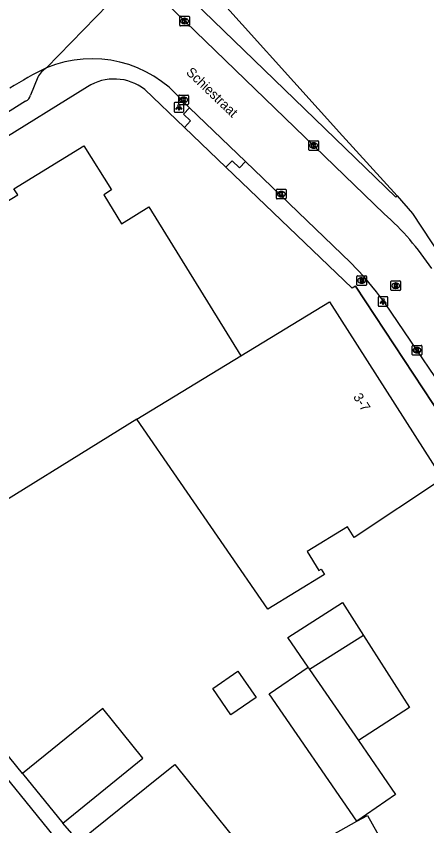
# Model space of a CAD drawing. Extents: x 157321 to 158827, y 386650 to 388532.
# Drawn here: x 157396.2 to 157438.5, y 387596.5 to 387680.1 of the extents above; entities that cross this region are included whole.
import ezdxf

# ---------------------------------------------------------------- set-up
doc = ezdxf.new("R2010")
doc.units = 0
for name, color, linetype in [('IMGEO_Brandkraan', 7, 'Continuous'), ('IMGEO_Erf', 7, 'Continuous'), ('IMGEO_Greppel_droge_sloot', 7, 'Continuous'), ('IMGEO_Groenvoorziening', 7, 'Continuous'), ('IMGEO_Kolk', 7, 'Continuous'), ('IMGEO_Lichtpunt', 7, 'Continuous'), ('IMGEO_Muur', 7, 'Continuous'), ('IMGEO_Openbare_ruimte_label', 7, 'Continuous'), ('IMGEO_Pand', 7, 'Continuous'), ('IMGEO_Pand_nummerreeks', 7, 'Continuous'), ('IMGEO_Rijbaan_lokaal_open', 7, 'Continuous'), ('IMGEO_Rioolput', 7, 'Continuous'), ('IMGEO_Voetpad_open', 7, 'Continuous')]:
    doc.layers.add(name, color=color, linetype=linetype)

msp = doc.modelspace()

# ---------------------------------------------------------------- linework, layer by layer
at = {"layer": 'IMGEO_Brandkraan'}
for p, q in [((157431.307, 387652.411), (157431.307, 387653.263)), ((157431.382, 387653.337), (157432.234, 387653.337)), ((157431.795, 387653.117), (157431.82, 387653.117)), ((157432.308, 387653.263), (157432.308, 387652.411)), ((157432.234, 387652.337), (157431.382, 387652.337)), ((157431.818, 387652.557), (157431.793, 387652.557))]:
    msp.add_line(p, q, dxfattribs=at)
for points in [[(157431.307, 387652.411), (157431.307, 387653.263)], [(157431.382, 387653.337), (157432.234, 387653.337)], [(157431.655, 387653.037), (157431.655, 387652.637), (157431.868, 387652.637)], [(157431.886, 387653.037), (157431.655, 387653.037)], [(157432.308, 387653.263), (157432.308, 387652.411)], [(157432.234, 387652.337), (157431.382, 387652.337)], [(157431.834, 387652.956), (157431.78, 387652.956), (157431.78, 387652.88)], [(157431.78, 387652.88), (157431.833, 387652.88)], [(157431.842, 387652.804), (157431.78, 387652.804), (157431.78, 387652.723)], [(157431.78, 387652.723), (157431.842, 387652.723)]]:
    msp.add_lwpolyline(points, dxfattribs=at)
for centre, radius, start, end in [((157431.384, 387653.261), 0.0765, 91.55205, 178.44795), ((157431.384, 387653.261), 0.0765, 91.55205, 178.44795), ((157431.89, 387652.892), 0.145, 59.4692, 91.53667), ((157431.915, 387652.939), 0.0922, 285.51372, 58.15012), ((157432.232, 387653.261), 0.0765, 1.55205, 88.44795), ((157432.232, 387653.261), 0.0765, 1.55205, 88.44795), ((157431.384, 387652.413), 0.0765, 181.55205, 268.44795), ((157431.384, 387652.413), 0.0765, 181.55205, 268.44795), ((157431.835, 387652.918), 0.0379, 267.82845, 90.93552), ((157431.843, 387652.763), 0.0404, 269.87594, 90.50774), ((157431.874, 387652.888), 0.251, 268.66757, 293.53466), ((157431.92, 387652.747), 0.105, 301.31148, 78.98903), ((157432.232, 387652.413), 0.0765, 271.55205, 358.44795), ((157432.232, 387652.413), 0.0765, 271.55205, 358.44795)]:
    msp.add_arc(centre, radius, start, end, dxfattribs=at)
for centre, major_axis, ratio, start_param, end_param in [((157431.794, 387652.837), (-0.387, 0.002), 0.722429, 4.712389, 7.853982), ((157431.819, 387652.837), (-0.39, 0.002), 0.717154, 1.570796, 4.712389)]:
    msp.add_ellipse(centre, major_axis=major_axis, ratio=ratio, start_param=start_param, end_param=end_param, dxfattribs=at)
at = {"layer": 'IMGEO_Erf'}
for points in [[(157396.827, 387601.943), (157374.839, 387629.111), (157367.841, 387637.744)], [(157402.618, 387594.917), (157400.97, 387596.826)]]:
    msp.add_lwpolyline(points, dxfattribs=at)
at = {"layer": 'IMGEO_Greppel_droge_sloot'}
msp.add_lwpolyline([(157364.956, 387637.663), (157366.252, 387637.187), (157406.382, 387587.613), (157407.121, 387586.787), (157407.417, 387584.957), (157406.631, 387583.97), (157405.344, 387583.565), (157404.654, 387583.712), (157404.061, 387584.031), (157403.357, 387584.76), (157364.055, 387633.408), (157363.304, 387634.511), (157362.971, 387635.617), (157363.13, 387636.647), (157363.942, 387637.488), (157364.956, 387637.663)], dxfattribs=at)
at = {"layer": 'IMGEO_Groenvoorziening'}
msp.add_lwpolyline([(157425.585, 387732.533), (157423.705, 387722.067), (157425.177, 387721.431), (157414.446, 387684.901), (157429.844, 387667.778), (157435.461, 387661.595)], dxfattribs=at)
at = {"layer": 'IMGEO_Kolk'}
for p, q in [((157413.036, 387679.217), (157413.036, 387680.069)), ((157413.111, 387680.143), (157413.963, 387680.143)), ((157413.524, 387679.923), (157413.549, 387679.923)), ((157414.037, 387680.069), (157414.037, 387679.217)), ((157413.963, 387679.143), (157413.111, 387679.143)), ((157413.547, 387679.363), (157413.522, 387679.363)), ((157412.936, 387671.077), (157412.936, 387671.929)), ((157413.011, 387672.003), (157413.863, 387672.003)), ((157413.424, 387671.783), (157413.449, 387671.783)), ((157413.937, 387671.929), (157413.937, 387671.077)), ((157413.863, 387671.003), (157413.011, 387671.003)), ((157413.447, 387671.223), (157413.422, 387671.223)), ((157426.355, 387666.354), (157426.355, 387667.206)), ((157426.43, 387667.28), (157427.282, 387667.28)), ((157427.356, 387667.206), (157427.356, 387666.354)), ((157426.866, 387666.5), (157426.841, 387666.5)), ((157426.843, 387667.06), (157426.868, 387667.06)), ((157427.282, 387666.28), (157426.43, 387666.28)), ((157423.011, 387661.349), (157423.011, 387662.201)), ((157423.086, 387662.275), (157423.938, 387662.275)), ((157424.012, 387662.201), (157424.012, 387661.349)), ((157423.522, 387661.495), (157423.497, 387661.495)), ((157423.499, 387662.055), (157423.524, 387662.055)), ((157423.938, 387661.275), (157423.086, 387661.275)), ((157437.019, 387645.218), (157437.019, 387646.07)), ((157437.094, 387646.144), (157437.946, 387646.144)), ((157437.507, 387645.924), (157437.532, 387645.924)), ((157438.02, 387646.07), (157438.02, 387645.218)), ((157437.946, 387645.144), (157437.094, 387645.144)), ((157437.53, 387645.364), (157437.505, 387645.364))]:
    msp.add_line(p, q, dxfattribs=at)
for points in [[(157413.036, 387679.217), (157413.036, 387680.069)], [(157413.111, 387680.143), (157413.963, 387680.143)], [(157413.357, 387679.843), (157413.48, 387679.843), (157413.48, 387679.692), (157413.61, 387679.843), (157413.774, 387679.843), (157413.628, 387679.692), (157413.781, 387679.443), (157413.629, 387679.443), (157413.544, 387679.607), (157413.48, 387679.54), (157413.48, 387679.443), (157413.357, 387679.443), (157413.357, 387679.843)], [(157414.037, 387680.069), (157414.037, 387679.217)], [(157413.963, 387679.143), (157413.111, 387679.143)], [(157412.936, 387671.077), (157412.936, 387671.929)], [(157413.011, 387672.003), (157413.863, 387672.003)], [(157413.257, 387671.703), (157413.38, 387671.703), (157413.38, 387671.552), (157413.51, 387671.703), (157413.674, 387671.703), (157413.528, 387671.552), (157413.681, 387671.303), (157413.529, 387671.303), (157413.444, 387671.467), (157413.38, 387671.4), (157413.38, 387671.303), (157413.257, 387671.303), (157413.257, 387671.703)], [(157413.937, 387671.929), (157413.937, 387671.077)], [(157413.863, 387671.003), (157413.011, 387671.003)], [(157426.355, 387666.354), (157426.355, 387667.206)], [(157426.43, 387667.28), (157427.282, 387667.28)], [(157427.356, 387667.206), (157427.356, 387666.354)], [(157426.676, 387666.98), (157426.799, 387666.98), (157426.799, 387666.829), (157426.929, 387666.98), (157427.093, 387666.98), (157426.947, 387666.829), (157427.1, 387666.58), (157426.948, 387666.58), (157426.863, 387666.744), (157426.799, 387666.677), (157426.799, 387666.58), (157426.676, 387666.58), (157426.676, 387666.98)], [(157427.282, 387666.28), (157426.43, 387666.28)], [(157423.011, 387661.349), (157423.011, 387662.201)], [(157423.086, 387662.275), (157423.938, 387662.275)], [(157424.012, 387662.201), (157424.012, 387661.349)], [(157423.332, 387661.975), (157423.455, 387661.975), (157423.455, 387661.824), (157423.585, 387661.975), (157423.749, 387661.975), (157423.603, 387661.824), (157423.756, 387661.575), (157423.604, 387661.575), (157423.519, 387661.739), (157423.455, 387661.672), (157423.455, 387661.575), (157423.332, 387661.575), (157423.332, 387661.975)], [(157423.938, 387661.275), (157423.086, 387661.275)], [(157437.019, 387645.218), (157437.019, 387646.07)], [(157437.094, 387646.144), (157437.946, 387646.144)], [(157437.34, 387645.844), (157437.463, 387645.844), (157437.463, 387645.693), (157437.593, 387645.844), (157437.757, 387645.844), (157437.611, 387645.693), (157437.764, 387645.444), (157437.612, 387645.444), (157437.527, 387645.608), (157437.463, 387645.541), (157437.463, 387645.444), (157437.34, 387645.444), (157437.34, 387645.844)], [(157438.02, 387646.07), (157438.02, 387645.218)], [(157437.946, 387645.144), (157437.094, 387645.144)]]:
    msp.add_lwpolyline(points, dxfattribs=at)
for centre, start, end in [((157413.113, 387680.067), 91.55205, 178.44795), ((157413.113, 387680.067), 91.55205, 178.44795), ((157413.961, 387680.067), 1.55205, 88.44795), ((157413.961, 387680.067), 1.55205, 88.44795), ((157413.113, 387679.219), 181.55205, 268.44795), ((157413.113, 387679.219), 181.55205, 268.44795), ((157413.961, 387679.219), 271.55205, 358.44795), ((157413.961, 387679.219), 271.55205, 358.44795), ((157413.013, 387671.927), 91.55205, 178.44795), ((157413.013, 387671.927), 91.55205, 178.44795), ((157413.861, 387671.927), 1.55205, 88.44795), ((157413.861, 387671.927), 1.55205, 88.44795), ((157413.013, 387671.079), 181.55205, 268.44795), ((157413.013, 387671.079), 181.55205, 268.44795), ((157413.861, 387671.079), 271.55205, 358.44795), ((157413.861, 387671.079), 271.55205, 358.44795), ((157426.432, 387667.204), 91.55205, 178.44795), ((157426.432, 387667.204), 91.55205, 178.44795), ((157427.28, 387667.204), 1.55205, 88.44795), ((157427.28, 387667.204), 1.55205, 88.44795), ((157426.432, 387666.356), 181.55205, 268.44795), ((157426.432, 387666.356), 181.55205, 268.44795), ((157427.28, 387666.356), 271.55205, 358.44795), ((157427.28, 387666.356), 271.55205, 358.44795), ((157423.088, 387662.199), 91.55205, 178.44795), ((157423.088, 387662.199), 91.55205, 178.44795), ((157423.936, 387662.199), 1.55205, 88.44795), ((157423.936, 387662.199), 1.55205, 88.44795), ((157423.088, 387661.351), 181.55205, 268.44795), ((157423.088, 387661.351), 181.55205, 268.44795), ((157423.936, 387661.351), 271.55205, 358.44795), ((157423.936, 387661.351), 271.55205, 358.44795), ((157437.096, 387646.068), 91.55205, 178.44795), ((157437.096, 387646.068), 91.55205, 178.44795), ((157437.944, 387646.068), 1.55205, 88.44795), ((157437.944, 387646.068), 1.55205, 88.44795), ((157437.096, 387645.22), 181.55205, 268.44795), ((157437.096, 387645.22), 181.55205, 268.44795), ((157437.944, 387645.22), 271.55205, 358.44795), ((157437.944, 387645.22), 271.55205, 358.44795)]:
    msp.add_arc(centre, 0.0765, start, end, dxfattribs=at)
for centre, major_axis, ratio, start_param, end_param in [((157413.523, 387679.643), (-0.387, 0.002), 0.722429, 4.712389, 7.853982), ((157413.548, 387679.643), (-0.39, 0.002), 0.717154, 1.570796, 4.712389), ((157413.423, 387671.503), (-0.387, 0.002), 0.722429, 4.712389, 7.853982), ((157413.448, 387671.503), (-0.39, 0.002), 0.717154, 1.570796, 4.712389), ((157426.842, 387666.78), (-0.387, 0.002), 0.722429, 4.712389, 7.853982), ((157426.867, 387666.78), (-0.39, 0.002), 0.717154, 1.570796, 4.712389), ((157423.498, 387661.775), (-0.387, 0.002), 0.722429, 4.712389, 7.853982), ((157423.523, 387661.775), (-0.39, 0.002), 0.717154, 1.570796, 4.712389), ((157437.506, 387645.644), (-0.387, 0.002), 0.722429, 4.712389, 7.853982), ((157437.531, 387645.644), (-0.39, 0.002), 0.717154, 1.570796, 4.712389)]:
    msp.add_ellipse(centre, major_axis=major_axis, ratio=ratio, start_param=start_param, end_param=end_param, dxfattribs=at)
at = {"layer": 'IMGEO_Lichtpunt'}
for p, q in [((157412.45, 387671.134), (157412.45, 387670.327)), ((157412.45, 387671.134), (157412.45, 387670.327)), ((157413.352, 387671.229), (157412.544, 387671.229)), ((157413.352, 387671.229), (157412.544, 387671.229)), ((157413.446, 387670.327), (157413.446, 387671.134)), ((157413.446, 387670.327), (157413.446, 387671.134)), ((157412.544, 387670.233), (157413.352, 387670.233)), ((157412.544, 387670.233), (157413.352, 387670.233)), ((157433.516, 387651.084), (157433.516, 387650.277)), ((157433.516, 387651.084), (157433.516, 387650.277)), ((157434.418, 387651.179), (157433.61, 387651.179)), ((157434.418, 387651.179), (157433.61, 387651.179)), ((157434.512, 387650.277), (157434.512, 387651.084)), ((157434.512, 387650.277), (157434.512, 387651.084)), ((157433.61, 387650.183), (157434.418, 387650.183)), ((157433.61, 387650.183), (157434.418, 387650.183))]:
    msp.add_line(p, q, dxfattribs=at)
for points in [[(157412.824, 387670.798), (157412.863, 387670.77), (157412.675, 387670.508), (157412.637, 387670.535), (157412.824, 387670.798)], [(157412.926, 387670.75), (157412.973, 387670.75), (157412.973, 387670.428), (157412.926, 387670.428), (157412.926, 387670.75)], [(157413.036, 387670.77), (157413.074, 387670.797), (157413.261, 387670.535), (157413.222, 387670.507), (157413.036, 387670.77)], [(157433.89, 387650.748), (157433.929, 387650.72), (157433.741, 387650.458), (157433.703, 387650.485), (157433.89, 387650.748)], [(157433.992, 387650.7), (157434.039, 387650.7), (157434.039, 387650.378), (157433.992, 387650.378), (157433.992, 387650.7)], [(157434.102, 387650.72), (157434.14, 387650.747), (157434.327, 387650.485), (157434.288, 387650.457), (157434.102, 387650.72)]]:
    msp.add_lwpolyline(points, dxfattribs=at)
for centre in [(157412.949, 387670.932), (157434.015, 387650.882)]:
    msp.add_circle(centre, 0.0994, dxfattribs=at)
for centre, start, end in [((157412.544, 387671.134), 90, 180), ((157412.544, 387671.134), 90, 180), ((157413.352, 387671.134), 0, 90), ((157413.352, 387671.134), 0, 90), ((157412.544, 387670.327), 180, 270), ((157412.544, 387670.327), 180, 270), ((157413.352, 387670.327), 270, 0), ((157413.352, 387670.327), 270, 360), ((157433.61, 387651.084), 90, 180), ((157433.61, 387651.084), 90, 180), ((157434.418, 387651.084), 0, 90), ((157434.418, 387651.084), 0, 90), ((157433.61, 387650.277), 180, 270), ((157433.61, 387650.277), 180, 270), ((157434.418, 387650.277), 270, 0), ((157434.418, 387650.277), 270, 360)]:
    msp.add_arc(centre, 0.0946, start, end, dxfattribs=at)
at = {"layer": 'IMGEO_Muur'}
msp.add_lwpolyline([(157431.16, 387652.274), (157441.141, 387637.118)], dxfattribs=at)
at = {"layer": 'IMGEO_Pand'}
for points in [[(157408.617, 387638.531), (157390.176, 387627.112), (157378.757, 387641.186), (157381.806, 387643.081), (157377.054, 387650.725), (157383.572, 387654.776), (157384.062, 387653.961), (157385.72, 387654.996), (157385.229, 387655.786), (157387.738, 387657.347), (157388.139, 387656.695), (157396.315, 387661.696), (157395.933, 387662.318), (157403.154, 387666.754), (157405.998, 387662.203), (157405.189, 387661.704), (157407.032, 387658.717), (157409.86, 387660.461), (157419.341, 387645.069)], [(157419.341, 387645.069), (157428.476, 387650.638), (157440.159, 387632.352), (157431.022, 387626.307), (157430.353, 387627.404), (157426.19, 387624.866), (157427.395, 387622.889), (157427.627, 387623.031), (157427.961, 387622.484), (157422.111, 387618.917), (157408.617, 387638.531)], [(157408.617, 387638.531), (157419.341, 387645.069)], [(157426.276, 387612.911), (157424.175, 387615.967), (157429.815, 387619.613), (157431.989, 387616.204)], [(157431.989, 387616.204), (157426.433, 387612.682)], [(157431.989, 387616.204), (157436.747, 387608.743), (157431.485, 387605.33)], [(157431.296, 387597.002), (157422.261, 387610.151), (157426.276, 387612.911)], [(157426.276, 387612.911), (157426.433, 387612.682)], [(157419.045, 387612.498), (157420.91, 387609.785), (157418.3, 387607.991), (157416.435, 387610.704), (157419.045, 387612.498)], [(157426.433, 387612.682), (157431.485, 387605.33)], [(157400.97, 387596.826), (157409.235, 387603.518), (157405.092, 387608.635), (157396.827, 387601.943)], [(157431.485, 387605.33), (157435.312, 387599.761), (157431.296, 387597.002)], [(157402.618, 387594.917), (157402.719, 387594.998), (157411.02, 387601.657), (157412.54, 387602.877), (157422.262, 387590.759), (157420.219, 387589.12), (157412.456, 387582.892), (157412.34, 387582.799), (157410.52, 387585.068)], [(157396.827, 387601.943), (157400.97, 387596.826)], [(157431.296, 387597.002), (157432.397, 387597.611), (157435.431, 387592.204), (157437.953, 387587.722), (157431.7, 387584.365), (157429.321, 387588.764), (157428.143, 387590.942), (157426.346, 387594.264), (157429.653, 387596.093), (157431.296, 387597.002)]]:
    msp.add_lwpolyline(points, dxfattribs=at)
at = {"layer": 'IMGEO_Rijbaan_lokaal_open'}
for points in [[(157399.304, 387674.807), (157405.65, 387681.348), (157409.849, 387690.039)], [(157434.138, 387659.746), (157412.586, 387680.561), (157412.173, 387680.984), (157411.604, 387681.662), (157411.098, 387682.388), (157410.659, 387683.156), (157410.349, 387683.832)], [(157414.051, 387670.696), (157413.31, 387671.395)], [(157419.814, 387665.122), (157414.051, 387670.696)], [(157442.615, 387638.112), (157434.281, 387650.428), (157433.944, 387650.859), (157433.339, 387651.683), (157432.066, 387653.223), (157430.656, 387654.695), (157419.814, 387665.122)]]:
    msp.add_lwpolyline(points, dxfattribs=at)
for centre, radius, start, end in [((157403.988, 387663.58), 12.165, 39.97424, 112.64348), ((157416.129, 387639.731), 38.903, 115.62531, 122.02517), ((157414.199, 387637.599), 29.801, 33.56971, 48.00307)]:
    msp.add_arc(centre, radius, start, end, dxfattribs=at)
at = {"layer": 'IMGEO_Rioolput'}
for p, q in [((157434.823, 387651.886), (157434.823, 387652.738)), ((157434.898, 387652.812), (157435.75, 387652.812)), ((157435.311, 387652.592), (157435.336, 387652.592)), ((157435.824, 387652.738), (157435.824, 387651.886)), ((157435.75, 387651.812), (157434.898, 387651.812)), ((157435.334, 387652.032), (157435.309, 387652.032))]:
    msp.add_line(p, q, dxfattribs=at)
for points in [[(157434.823, 387651.886), (157434.823, 387652.738)], [(157434.898, 387652.812), (157435.75, 387652.812)], [(157435.412, 387652.51), (157435.16, 387652.512), (157435.16, 387652.112)], [(157435.16, 387652.112), (157435.284, 387652.112), (157435.284, 387652.274), (157435.295, 387652.274)], [(157435.338, 387652.431), (157435.284, 387652.431), (157435.284, 387652.35)], [(157435.284, 387652.35), (157435.336, 387652.35)], [(157435.342, 387652.245), (157435.413, 387652.112), (157435.553, 387652.112), (157435.488, 387652.238)], [(157435.824, 387652.738), (157435.824, 387651.886)], [(157435.75, 387651.812), (157434.898, 387651.812)]]:
    msp.add_lwpolyline(points, dxfattribs=at)
for centre, radius, start, end in [((157434.9, 387652.736), 0.0765, 91.55205, 178.44795), ((157434.9, 387652.736), 0.0765, 91.55205, 178.44795), ((157435.294, 387652.221), 0.0533, 26.02933, 88.69889), ((157435.32, 387652.539), 0.19, 274.7715, 282.96867), ((157435.344, 387652.335), 0.0964, 77.00612, 93.18647), ((157435.358, 387652.392), 0.0378, 276.66336, 79.67722), ((157435.411, 387652.4), 0.109, 350.36119, 89.41601), ((157435.409, 387652.4), 0.112, 277.58423, 350.98172), ((157435.393, 387652.185), 0.108, 29.51342, 73.79051), ((157435.748, 387652.736), 0.0765, 1.55205, 88.44795), ((157435.748, 387652.736), 0.0765, 1.55205, 88.44795), ((157434.9, 387651.888), 0.0765, 181.55205, 268.44795), ((157434.9, 387651.888), 0.0765, 181.55205, 268.44795), ((157435.748, 387651.888), 0.0765, 271.55205, 358.44795), ((157435.748, 387651.888), 0.0765, 271.55205, 358.44795)]:
    msp.add_arc(centre, radius, start, end, dxfattribs=at)
for centre, major_axis, ratio, start_param, end_param in [((157435.31, 387652.312), (-0.387, 0.002), 0.722429, 4.712389, 7.853982), ((157435.335, 387652.312), (-0.39, 0.002), 0.717154, 1.570796, 4.712389)]:
    msp.add_ellipse(centre, major_axis=major_axis, ratio=ratio, start_param=start_param, end_param=end_param, dxfattribs=at)
at = {"layer": 'IMGEO_Voetpad_open'}
for points in [[(157413.382, 387682.718), (157435.322, 387661.449), (157435.461, 387661.595)], [(157398.39, 387673.837), (157397.646, 387671.984)], [(157403.516, 387672.84), (157393.961, 387666.912)], [(157413.521, 387668.656), (157409.427, 387672.566)], [(157397.132, 387671.373), (157392.89, 387668.729)], [(157414.051, 387670.696), (157413.413, 387670.031), (157414.154, 387669.323), (157413.521, 387668.656)], [(157417.795, 387664.547), (157413.521, 387668.656)], [(157417.795, 387664.547), (157418.433, 387665.204), (157419.194, 387664.469), (157419.814, 387665.122)], [(157441.141, 387637.118), (157431.16, 387652.274), (157430.814, 387652.063), (157417.795, 387664.547)], [(157435.461, 387661.595), (157437.054, 387659.761), (157448.936, 387641.697), (157452.491, 387636.294), (157452.692, 387635.988)]]:
    msp.add_lwpolyline(points, dxfattribs=at)
for centre, radius, start, end in [((157400.673, 387672.602), 2.596, 121.82646, 151.57865), ((157406.281, 387668.586), 5.073, 51.67177, 123.02022), ((157396.838, 387672.142), 0.823, 290.92345, 348.93251)]:
    msp.add_arc(centre, radius, start, end, dxfattribs=at)

# ---------------------------------------------------------------- texts
at = {"layer": 'IMGEO_Openbare_ruimte_label'}
msp.add_text('Schiestraat', height=1, rotation=316.21543, dxfattribs=at).set_placement((157413.618, 387674.252))
at = {"layer": 'IMGEO_Pand_nummerreeks'}
msp.add_text('3-7', height=1, rotation=302.48077, dxfattribs=at).set_placement((157430.888, 387640.833))

doc.saveas('drawing.dxf')
